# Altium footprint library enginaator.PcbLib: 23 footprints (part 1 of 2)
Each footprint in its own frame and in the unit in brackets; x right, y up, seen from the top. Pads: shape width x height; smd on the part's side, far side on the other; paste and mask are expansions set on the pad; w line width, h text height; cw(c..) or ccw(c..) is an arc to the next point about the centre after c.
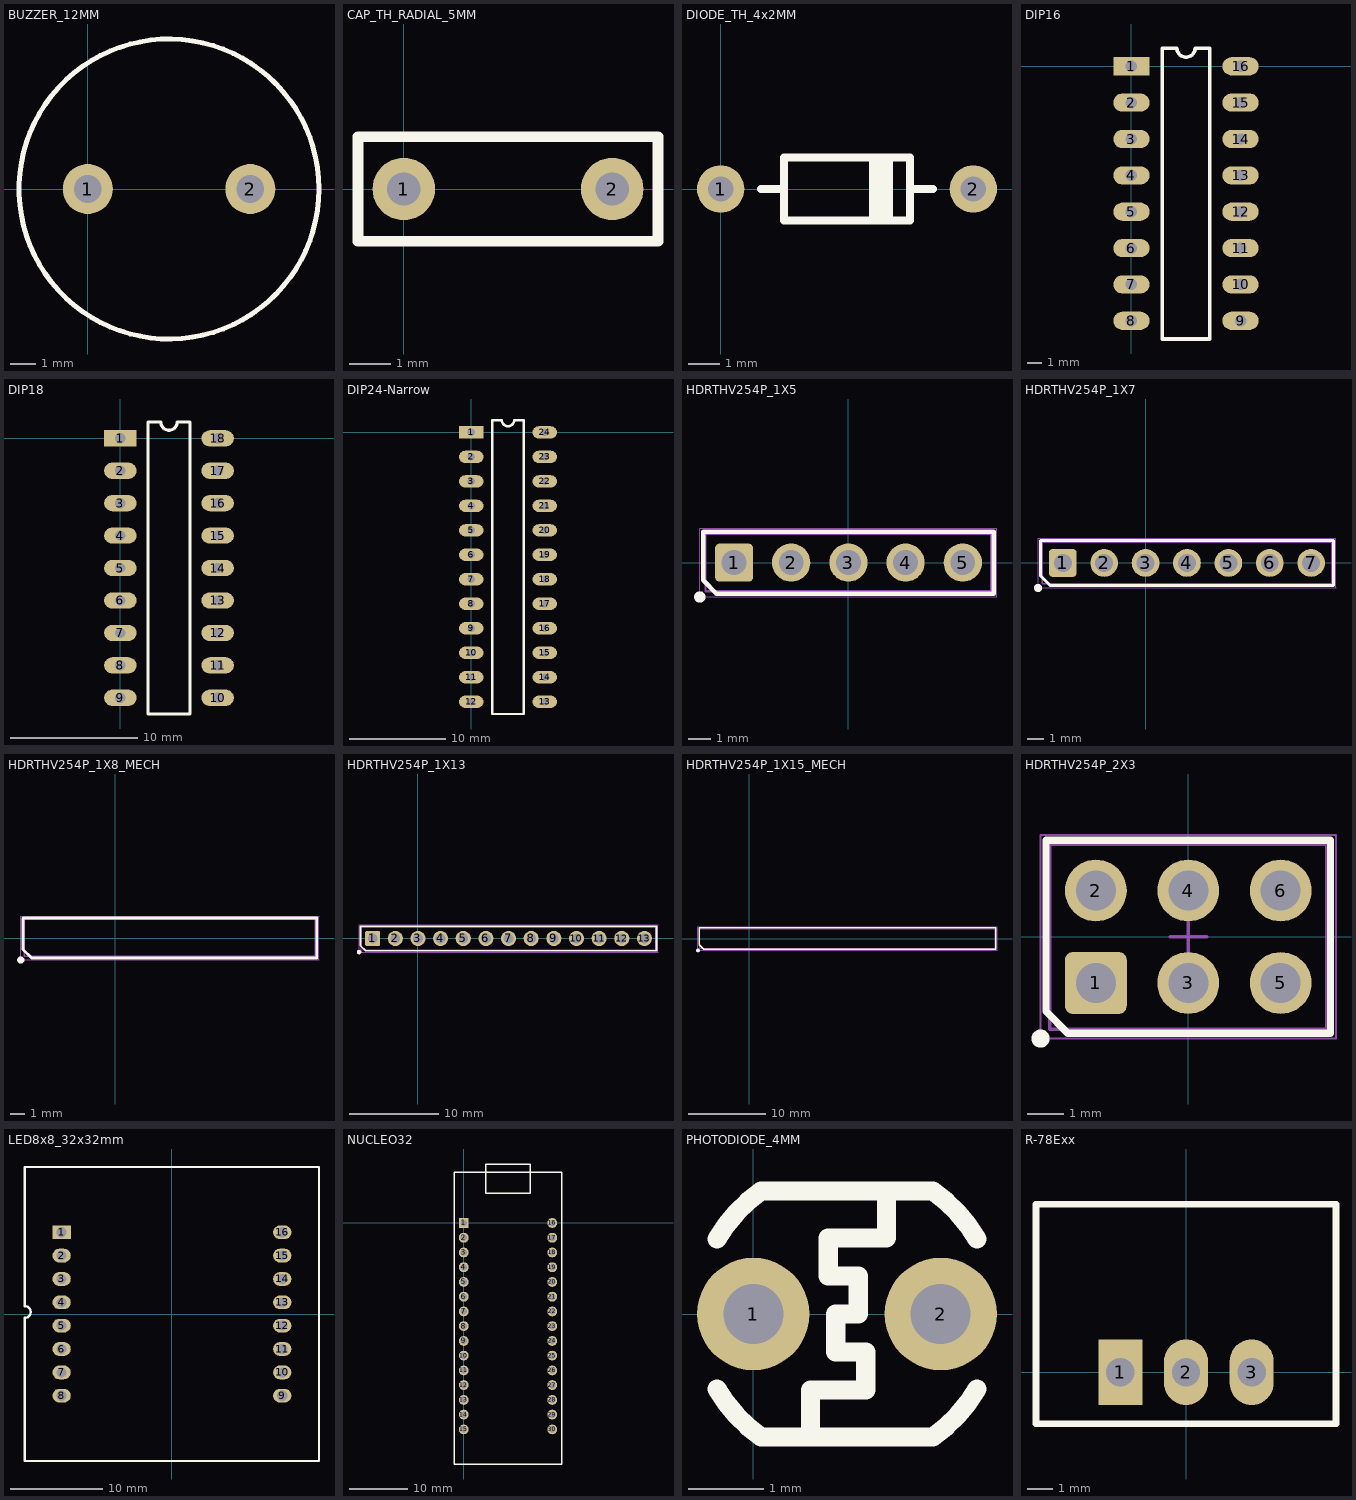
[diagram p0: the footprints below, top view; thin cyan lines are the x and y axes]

## BUZZER_12MM [mm]
pads (2):
  round 2 hole 1.1: 1(0,0) 2(6.5,0)
Top Overlay:
  circle w0.2: c3.25,0 r6

## CAP_TH_RADIAL_5MM [mm]
pads (2):
  round 1.5 hole 0.8: 1(0,0) 2(5,0)
Top Overlay:
  lines w0.254: -1.1,-1.25 -1.1,1.25 0,1.25 5,1.25 6.1,1.25 6.1,-1.25 5,-1.25 0,-1.25 -1.1,-1.25

## DIODE_TH_4x2MM [mm]
pads (2):
  round 1.5 hole 0.8: 1(0,0) 2(8,0)
Top Overlay:
  lines w0.254: 1.27,0 2,0 ; 4.826,-1 4.826,1 ; 5.08,-1 5.08,1 ; 5.334,-1 5.334,0.984 ; 6,0 6.73,0 ; 2,0 2,-1 6,-1 6,1 2,1 2,0

## DIP16 [mm]
pads (16):
  rect 2.54x1.27 hole 0.8: 1(0,0)
  oval 2.54x1.27 hole 0.8: 2(0,-2.54) 3(0,-5.08) 4(0,-7.62) 5(0,-10.16) 6(0,-12.7) 7(0,-15.24) 8(0,-17.78) 9(7.62,-17.78) 10(7.62,-15.24) 11(7.62,-12.7) 12(7.62,-10.16) 13(7.62,-7.62) 14(7.62,-5.08) 15(7.62,-2.54) 16(7.62,0)
Top Overlay:
  lines w0.254: 2.159,-19.05 5.461,-19.05 5.461,1.27 4.445,1.27 cw(c3.81,1.27) 3.175,1.27 2.159,1.27 2.159,-19.05

## DIP18 [mm]
pads (18):
  rect 2.54x1.27 hole 0.8: 1(0,0)
  oval 2.54x1.27 hole 0.8: 2(0,-2.54) 3(0,-5.08) 4(0,-7.62) 5(0,-10.16) 6(0,-12.7) 7(0,-15.24) 8(0,-17.78) 9(0,-20.32) 10(7.62,-20.32) 11(7.62,-17.78) 12(7.62,-15.24) 13(7.62,-12.7) 14(7.62,-10.16) 15(7.62,-7.62) 16(7.62,-5.08) 17(7.62,-2.54) 18(7.62,0)
Top Overlay:
  lines w0.254: 2.159,-21.59 5.461,-21.59 5.461,1.27 4.445,1.27 cw(c3.81,1.27) 3.175,1.27 2.159,1.27 2.159,-21.59

## DIP24-Narrow [mm]
pads (24):
  rect 2.54x1.27 hole 0.8: 1(0,0)
  oval 2.54x1.27 hole 0.8: 2(0,-2.54) 3(0,-5.08) 4(0,-7.62) 5(0,-10.16) 6(0,-12.7) 7(0,-15.24) 8(0,-17.78) 9(0,-20.32) 10(0,-22.86) 11(0,-25.4) 12(0,-27.94) 13(7.62,-27.94) 14(7.62,-25.4) 15(7.62,-22.86) 16(7.62,-20.32) 17(7.62,-17.78) 18(7.62,-15.24) 19(7.62,-12.7) 20(7.62,-10.16) 21(7.62,-7.62) 22(7.62,-5.08) 23(7.62,-2.54) 24(7.62,0)
Top Overlay:
  lines w0.254: 2.159,-29.21 2.159,1.27 3.175,1.27 ccw(c3.81,1.27) 4.445,1.27 5.461,1.27 5.461,-29.21 2.159,-29.21

## HDRTHV254P_1X5 [mm] "Header, vertical, through-hole, 2.54mm pitch, 1X5"
pads (5):
  rrect25% 1.7x1.7 hole 1.1: 1(-5.08,0)
  round 1.7 hole 1.1: 2(-2.54,0) 3(0,0) 4(2.54,0) 5(5.08,0)
Top Overlay:
  circle w0.25: c-6.6,-1.525 r0.125
  lines w0.2: -6.45,-0.79 -5.865,-1.375 6.45,-1.375 6.45,1.375 -6.45,1.375 -6.45,-0.79
Mechanical 13:
  circle w0.1: c-5.08,0 r0.5
  lines w0.1: 6.3,-1.27 -6.35,-1.27 -6.35,1.27 6.3,1.27 ; 6.35,-1.27 6.35,1.27
Mechanical 15:
  lines w0.05: -6.6,-1.525 6.6,-1.525 6.6,1.525 -6.6,1.525 -6.6,-1.525
  lines w0.1: -0.5,0 0.5,0 ; 0,-0.5 0,0.5
3D body "Pin Header 1x2 TH Pitch 2.54mm.stp": height 9.5, standoff -3.2, extent -1.27,-1.27 3.81,1.27
3D body "Pin Header 1x2 TH Pitch 2.54mm.stp": height 9.5, standoff -3.2, extent -6.35,-1.27 -1.27,1.27
3D body "Pin Header 1x2 TH Pitch 2.54mm.stp": height 9.5, standoff -3.2, extent 1.27,-1.27 6.35,1.27

## HDRTHV254P_1X7 [mm] "Header, vertical, through-hole, 2.54mm pitch, 1X5"
pads (7):
  rrect25% 1.7x1.7 hole 1.1: 1(-5.08,0)
  round 1.7 hole 1.1: 2(-2.54,0) 3(0,0) 4(2.54,0) 5(5.08,0) 6(7.62,0) 7(10.16,0)
Top Overlay:
  circle w0.25: c-6.6,-1.525 r0.125
  lines w0.2: -6.45,-0.79 -5.865,-1.375 11.53,-1.375 11.53,1.375 -6.45,1.375 -6.45,-0.79
Mechanical 13:
  circle w0.1: c-5.08,0 r0.5
  lines w0.1: 11.405,-1.27 -6.35,-1.27 -6.35,1.27 11.425,1.27 ; 11.43,-1.27 11.43,1.27
Mechanical 15:
  lines w0.05: 11.659,1.525 -6.6,1.525 -6.6,-1.525 11.684,-1.525 ; 11.68,-1.525 11.68,1.525
  lines w0.1: -0.5,0 0.5,0 ; 0,-0.5 0,0.5
3D body "Pin Header 1x2 TH Pitch 2.54mm.stp": height 9.5, standoff -3.2, extent 6.35,-1.27 11.43,1.27
3D body "Pin Header 1x2 TH Pitch 2.54mm.stp": height 9.5, standoff -3.2, extent -1.27,-1.27 3.81,1.27
3D body "Pin Header 1x2 TH Pitch 2.54mm.stp": height 9.5, standoff -3.2, extent -6.35,-1.27 -1.27,1.27
3D body "Pin Header 1x2 TH Pitch 2.54mm.stp": height 9.5, standoff -3.2, extent 1.27,-1.27 6.35,1.27

## HDRTHV254P_1X8_MECH [mm] "Header, vertical, through-hole, 2.54mm pitch, 1X5"
Top Overlay:
  circle w0.25: c-6.6,-1.525 r0.125
  lines w0.2: -6.45,-0.79 -6.45,1.4 14.07,1.4 14.07,-1.4 -5.84,-1.4 -6.45,-0.79
Mechanical 13:
  lines w0.1: 13.9,-1.27 -6.35,-1.27 -6.35,1.3 13.97,1.3 13.97,-1.27
Mechanical 15:
  lines w0.05: 14.22,-1.525 14.22,1.525 ; 14.228,-1.525 -6.6,-1.525 -6.6,1.525 14.228,1.525

## HDRTHV254P_1X13 [mm] "Header, vertical, through-hole, 2.54mm pitch, 1X5"
pads (13):
  rrect25% 1.7x1.7 hole 1.1: 1(-5.08,0)
  round 1.7 hole 1.1: 2(-2.54,0) 3(0,0) 4(2.54,0) 5(5.08,0) 6(7.62,0) 7(10.16,0) 8(12.7,0) 9(15.24,0) 10(17.78,0) 11(20.32,0) 12(22.86,0) 13(25.4,0)
Top Overlay:
  circle w0.25: c-6.6,-1.525 r0.125
  lines w0.2: -6.45,-0.79 -6.45,1.375 26.77,1.375 26.77,-1.375 -5.865,-1.375 -6.45,-0.79
Mechanical 13:
  circle w0.1: c-5.08,0 r0.5
  lines w0.1: 26.665,-1.27 -6.35,-1.27 -6.35,1.27 26.665,1.27 ; 26.67,-1.27 26.67,1.27
Mechanical 15:
  lines w0.05: 26.92,-1.525 26.92,1.525 ; 26.924,-1.525 -6.6,-1.525 -6.6,1.525 26.924,1.525
  lines w0.1: -0.5,0 0.5,0 ; 0,-0.5 0,0.5
3D body "Pin Header 1x2 TH Pitch 2.54mm.stp": height 9.5, standoff -3.2, extent 1.27,-1.27 6.35,1.27
3D body "Pin Header 1x2 TH Pitch 2.54mm.stp": height 9.5, standoff -3.2, extent -6.35,-1.27 -1.27,1.27
3D body "Pin Header 1x2 TH Pitch 2.54mm.stp": height 9.5, standoff -3.2, extent -1.27,-1.27 3.81,1.27
3D body "Pin Header 1x2 TH Pitch 2.54mm.stp": height 9.5, standoff -3.2, extent 6.35,-1.27 11.43,1.27
3D body "Pin Header 1x2 TH Pitch 2.54mm.stp": height 9.5, standoff -3.2, extent 11.43,-1.27 16.51,1.27
3D body "Pin Header 1x2 TH Pitch 2.54mm.stp": height 9.5, standoff -3.2, extent 16.51,-1.27 21.59,1.27
3D body "Pin Header 1x2 TH Pitch 2.54mm.stp": height 9.5, standoff -3.2, extent 21.59,-1.27 26.67,1.27

## HDRTHV254P_1X15_MECH [mm] "Header, vertical, through-hole, 2.54mm pitch, 1X5"
Top Overlay:
  circle w0.25: c-6.6,-1.525 r0.125
  lines w0.2: -6.45,-0.79 -5.865,-1.375 31.85,-1.375 31.85,1.375 -6.45,1.375 -6.45,-0.79
Mechanical 13:
  lines w0.1: 31.745,-1.27 -6.35,-1.27 -6.35,1.27 31.745,1.27 ; 31.75,-1.27 31.75,1.27
Mechanical 15:
  lines w0.05: -6.6,-1.525 32,-1.525 32,1.525 -6.6,1.525 -6.6,-1.525

## HDRTHV254P_2X3 [mm] "Header, vertical, through-hole, 2.54mm pitch, 2X5"
pads (6):
  rrect25% 1.7x1.7 hole 1.1: 1(-2.54,-1.27)
  round 1.7 hole 1.1: 2(-2.54,1.27) 3(0,-1.27) 4(0,1.27) 5(2.54,-1.27) 6(2.54,1.27)
Top Overlay:
  circle w0.25: c-4.06,-2.8 r0.125
  lines w0.2: -3.91,-2.05 -3.31,-2.65 3.91,-2.65 3.91,2.65 -3.91,2.65 -3.91,-2.05
Mechanical 13:
  circle w0.1: c-2.54,-1.27 r0.5
  lines w0.1: -3.81,-2.54 3.81,-2.54 3.81,2.54 -3.81,2.54 -3.81,-2.54
Mechanical 15:
  lines w0.05: -4.06,-2.8 4.06,-2.8 4.06,2.8 -4.06,2.8 -4.06,-2.8
  lines w0.1: -0.5,0 0.5,0 ; 0,-0.5 0,0.5
3D body "Pin Header 1x2 TH Pitch 2.54mm.stp": height 9.5, standoff -3.2, extent -1.27,-2.54 1.27,2.54
3D body "Pin Header 1x2 TH Pitch 2.54mm.stp": height 9.5, standoff -3.2, extent -3.81,-2.54 -1.27,2.54
3D body "Pin Header 1x2 TH Pitch 2.54mm.stp": height 9.5, standoff -3.2, extent 1.27,-2.54 3.81,2.54

## LED8x8_32x32mm [mm]
pads (16):
  rect 2x1.5 hole 1.1: 1(-12,8.89)
  oval 2x1.5 hole 1.1: 2(-12,6.35) 3(-12,3.81) 4(-12,1.27) 5(-12,-1.27) 6(-12,-3.81) 7(-12,-6.35) 8(-12,-8.89) 9(12,-8.89) 10(12,-6.35) 11(12,-3.81) 12(12,-1.27) 13(12,1.27) 14(12,3.81) 15(12,6.35) 16(12,8.89)
Top Overlay:
  lines w0.254: -16,-16 -16,-0.415 ccw(c-16,0.22) -16,0.855 -16,16 16,16 16,-16 -16,-16

## NUCLEO32 [mm]
pads (30):
  rect 1.7x1.7 hole 1.1: 1(0,0)
  round 1.7 hole 1.1: 2(0,-2.54) 3(0,-5.08) 4(0,-7.62) 5(0,-10.16) 6(0,-12.7) 7(0,-15.24) 8(0,-17.78) 9(0,-20.32) 10(0,-22.86) 11(0,-25.4) 12(0,-27.94) 13(0,-30.48) 14(0,-33.02) 15(0,-35.56) 16(15.24,0) 17(15.24,-2.54) 18(15.24,-5.08) 19(15.24,-7.62) 20(15.24,-10.16) 21(15.24,-12.7) 22(15.24,-15.24) 23(15.24,-17.78) 24(15.24,-20.32) 25(15.24,-22.86) 26(15.24,-25.4) 27(15.24,-27.94) 28(15.24,-30.48) 29(15.24,-33.02) 30(15.24,-35.56)
Top Overlay:
  lines w0.254: -1.651,-41.529 -1.651,8.763 16.891,8.763 16.891,-41.529 -1.651,-41.529 ; 3.81,5.08 3.81,10.16 11.43,10.16 11.43,5.08 3.81,5.08

## PHOTODIODE_4MM [mm]
pads (2):
  round 1.5 hole 0.8: 1(0,0) 2(2.5,0)
Top Overlay:
  lines w0.254: -0.482,-1 ccw(c1.25,0) 0.103,-1.638 2.397,-1.638 ccw(c1.25,0) 2.982,-1 ; -0.482,1 cw(c1.25,0) 0.103,1.638 2.397,1.638 cw(c1.25,0) 2.982,1 ; 0.762,-1.638 0.762,-1.016 1.5,-1.016 1.5,-0.508 1.1,-0.508 1.1,0 1.4,0 1.4,0.508 1,0.508 1,1.016 1.778,1.016 1.778,1.638

## R-78Exx [mm]
pads (3):
  rect 1.7x2.54 hole 1.1: 1(-2.54,0)
  oval 1.7x2.54 hole 1.1: 2(0,0) 3(2.54,0)
Top Overlay:
  lines w0.254: -5.8,-2 -5.8,6.5 5.8,6.5 5.8,-2 -5.8,-2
